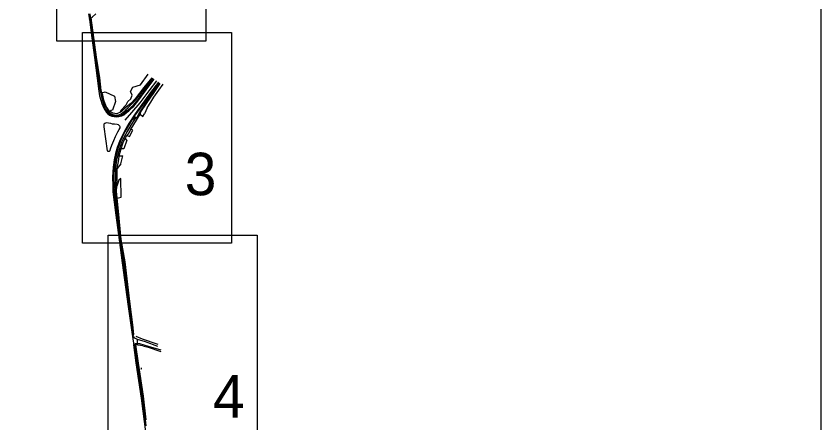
# Model space of a CAD drawing. Extents: x -866693 to -866303, y -1041966 to -1040244.
# Drawn here: x -866389.8 to -866333, y -1041534.9 to -1041506.2 of the extents above; entities that cross this region are included whole.
import ezdxf

# ---------------------------------------------------------------- set-up
doc = ezdxf.new("R2010")
doc.units = 0
doc.layers.add('Formát', color=7, linetype='Continuous')
doc.layers.add('Legenda', color=7, linetype='Continuous')

msp = doc.modelspace()

# ---------------------------------------------------------------- linework, layer by layer
at = {"layer": 'Formát'}
msp.add_lwpolyline([(-866543.01, -1041383.964), (-866333.01, -1041383.964), (-866333.01, -1041680.964), (-866543.01, -1041680.964)], close=True, dxfattribs=at)
at = {"layer": 'Legenda'}
for p, q in [((-866384.553, -1041506.047), (-866384.51, -1041506.433)), ((-866384.388, -1041506.26), (-866384.134, -1041506.041)), ((-866384.589, -1041506.446), (-866384.553, -1041506.379)), ((-866384.589, -1041506.446), (-866384.413, -1041507.37)), ((-866384.553, -1041506.379), (-866384.463, -1041506.308)), ((-866384.51, -1041506.433), (-866384.368, -1041507.364)), ((-866384.463, -1041506.308), (-866384.388, -1041506.26)), ((-866384.319, -1041507.359), (-866384.463, -1041506.308)), ((-866384.413, -1041507.37), (-866384.18, -1041509.114)), ((-866384.368, -1041507.364), (-866384.131, -1041509.098)), ((-866384.086, -1041509.097), (-866384.319, -1041507.359)), ((-866384.18, -1041509.114), (-866383.977, -1041510.562)), ((-866384.131, -1041509.098), (-866383.91, -1041510.543)), ((-866383.863, -1041510.544), (-866384.086, -1041509.097)), ((-866383.977, -1041510.562), (-866383.832, -1041511.476)), ((-866383.91, -1041510.543), (-866383.774, -1041511.45)), ((-866383.759, -1041511.453), (-866383.863, -1041510.544)), ((-866380.983, -1041511.048), (-866380.445, -1041510.294)), ((-866380.192, -1041510.544), (-866380.744, -1041511.231)), ((-866380.688, -1041511.307), (-866380.128, -1041510.566)), ((-866380.614, -1041511.367), (-866380.067, -1041510.598)), ((-866381.697, -1041511.521), (-866381.537, -1041511.209)), ((-866381.537, -1041511.209), (-866380.983, -1041511.048)), ((-866379.869, -1041510.753), (-866380.41, -1041511.478)), ((-866379.662, -1041510.902), (-866380.215, -1041511.627)), ((-866379.628, -1041510.945), (-866380.157, -1041511.689)), ((-866380.116, -1041511.717), (-866379.595, -1041510.958)), ((-866379.687, -1041511.426), (-866379.392, -1041510.988)), ((-866383.832, -1041511.476), (-866383.766, -1041511.793)), ((-866383.774, -1041511.45), (-866383.695, -1041511.778)), ((-866383.703, -1041511.615), (-866383.759, -1041511.453)), ((-866383.703, -1041511.615), (-866383.468, -1041511.542)), ((-866383.651, -1041511.774), (-866383.703, -1041511.615)), ((-866383.695, -1041511.778), (-866383.599, -1041512.119)), ((-866383.575, -1041512.118), (-866383.651, -1041511.774)), ((-866383.468, -1041511.542), (-866382.82, -1041511.84)), ((-866381.575, -1041511.767), (-866381.697, -1041511.521)), ((-866381.671, -1041512.027), (-866381.575, -1041511.767)), ((-866380.744, -1041511.231), (-866381.364, -1041512.04)), ((-866381.314, -1041512.109), (-866380.688, -1041511.307)), ((-866381.221, -1041512.17), (-866380.614, -1041511.367)), ((-866380.215, -1041511.627), (-866381.149, -1041512.883)), ((-866380.41, -1041511.478), (-866381.036, -1041512.316)), ((-866380.157, -1041511.689), (-866381.032, -1041512.948)), ((-866380.255, -1041511.906), (-866380.116, -1041511.717)), ((-866380.043, -1041511.916), (-866379.687, -1041511.426)), ((-866383.766, -1041511.793), (-866383.695, -1041512.106)), ((-866383.695, -1041512.106), (-866383.625, -1041512.32)), ((-866383.625, -1041512.32), (-866383.531, -1041512.609)), ((-866383.599, -1041512.119), (-866383.528, -1041512.332)), ((-866383.497, -1041512.324), (-866383.575, -1041512.118)), ((-866383.528, -1041512.332), (-866383.422, -1041512.587)), ((-866383.396, -1041512.576), (-866383.497, -1041512.324)), ((-866382.743, -1041512.227), (-866382.968, -1041512.839)), ((-866382.82, -1041511.84), (-866382.743, -1041512.227)), ((-866381.678, -1041512.349), (-866382.122, -1041512.705)), ((-866381.986, -1041512.448), (-866381.878, -1041512.215)), ((-866381.878, -1041512.215), (-866381.671, -1041512.027)), ((-866381.364, -1041512.04), (-866381.678, -1041512.349)), ((-866381.036, -1041512.316), (-866381.619, -1041512.989)), ((-866381.562, -1041512.366), (-866381.314, -1041512.109)), ((-866381.51, -1041512.49), (-866381.221, -1041512.17)), ((-866380.957, -1041512.958), (-866380.255, -1041511.906)), ((-866380.527, -1041512.671), (-866380.26, -1041512.266)), ((-866380.26, -1041512.266), (-866380.043, -1041511.916)), ((-866383.531, -1041512.609), (-866383.454, -1041512.781)), ((-866383.454, -1041512.781), (-866383.346, -1041512.954)), ((-866383.422, -1041512.587), (-866383.345, -1041512.753)), ((-866383.297, -1041512.726), (-866383.396, -1041512.576)), ((-866383.345, -1041512.753), (-866383.238, -1041512.925)), ((-866383.189, -1041512.867), (-866383.297, -1041512.726)), ((-866383.238, -1041512.925), (-866383.185, -1041512.988)), ((-866383.141, -1041512.921), (-866383.189, -1041512.867)), ((-866383.051, -1041512.864), (-866383.141, -1041512.921)), ((-866383.059, -1041512.975), (-866383.141, -1041512.921)), ((-866382.968, -1041512.839), (-866383.051, -1041512.864)), ((-866382.398, -1041512.881), (-866381.986, -1041512.448)), ((-866382.353, -1041512.947), (-866382.398, -1041512.881)), ((-866382.122, -1041512.705), (-866382.353, -1041512.947)), ((-866382.229, -1041512.993), (-866382.078, -1041512.884)), ((-866382.184, -1041513.097), (-866381.872, -1041512.824)), ((-866382.106, -1041512.975), (-866382.052, -1041512.925)), ((-866381.977, -1041512.867), (-866382.101, -1041512.97)), ((-866381.956, -1041512.888), (-866382.08, -1041512.991)), ((-866382.078, -1041512.884), (-866382.032, -1041512.808)), ((-866382.078, -1041512.884), (-866382.044, -1041512.917)), ((-866382.052, -1041512.925), (-866382.044, -1041512.917)), ((-866382.044, -1041512.917), (-866382.034, -1041512.909)), ((-866382.034, -1041512.909), (-866381.977, -1041512.867)), ((-866382.032, -1041512.808), (-866381.883, -1041512.663)), ((-866381.956, -1041512.888), (-866381.977, -1041512.867)), ((-866381.883, -1041512.663), (-866381.68, -1041512.483)), ((-866381.872, -1041512.824), (-866381.648, -1041512.62)), ((-866381.68, -1041512.483), (-866381.562, -1041512.366)), ((-866381.648, -1041512.62), (-866381.51, -1041512.49)), ((-866381.149, -1041512.883), (-866381.377, -1041513.194)), ((-866380.527, -1041512.671), (-866380.696, -1041513.08)), ((-866383.346, -1041512.954), (-866383.235, -1041513.047)), ((-866383.235, -1041513.047), (-866383.139, -1041513.124)), ((-866383.185, -1041512.988), (-866383.085, -1041513.057)), ((-866383.139, -1041513.124), (-866382.986, -1041513.201)), ((-866383.085, -1041513.057), (-866382.939, -1041513.128)), ((-866382.903, -1041513.052), (-866383.059, -1041512.975)), ((-866382.986, -1041513.201), (-866382.845, -1041513.234)), ((-866382.939, -1041513.128), (-866382.831, -1041513.161)), ((-866382.804, -1041513.072), (-866382.903, -1041513.052)), ((-866382.845, -1041513.234), (-866382.698, -1041513.246)), ((-866382.831, -1041513.161), (-866382.693, -1041513.18)), ((-866382.652, -1041513.081), (-866382.804, -1041513.072)), ((-866382.698, -1041513.246), (-866382.504, -1041513.232)), ((-866382.693, -1041513.18), (-866382.512, -1041513.159)), ((-866382.353, -1041512.947), (-866382.652, -1041513.081)), ((-866382.512, -1041513.159), (-866382.342, -1041513.092)), ((-866382.504, -1041513.232), (-866382.319, -1041513.178)), ((-866382.342, -1041513.092), (-866382.229, -1041512.993)), ((-866382.319, -1041513.178), (-866382.184, -1041513.097)), ((-866382.106, -1041512.975), (-866382.101, -1041512.97)), ((-866382.08, -1041512.991), (-866382.106, -1041512.975)), ((-866382.08, -1041512.991), (-866382.101, -1041512.97)), ((-866381.619, -1041512.989), (-866382.093, -1041513.536)), ((-866381.377, -1041513.194), (-866381.76, -1041513.801)), ((-866381.357, -1041513.418), (-866381.656, -1041513.89)), ((-866381.522, -1041513.97), (-866381.019, -1041513.103)), ((-866381.353, -1041513.303), (-866381.469, -1041513.459)), ((-866381.469, -1041513.459), (-866381.447, -1041513.476)), ((-866381.469, -1041513.459), (-866381.449, -1041513.477)), ((-866381.333, -1041513.321), (-866381.449, -1041513.477)), ((-866381.449, -1041513.477), (-866381.447, -1041513.476)), ((-866381.447, -1041513.476), (-866381.395, -1041513.413)), ((-866381.381, -1041513.399), (-866381.395, -1041513.413)), ((-866381.369, -1041513.379), (-866381.381, -1041513.399)), ((-866381.357, -1041513.418), (-866381.381, -1041513.399)), ((-866381.333, -1041513.322), (-866381.369, -1041513.379)), ((-866381.253, -1041513.346), (-866381.357, -1041513.418)), ((-866381.333, -1041513.321), (-866381.353, -1041513.303)), ((-866381.353, -1041513.303), (-866381.333, -1041513.322)), ((-866381.333, -1041513.322), (-866381.333, -1041513.321)), ((-866381.032, -1041512.948), (-866381.253, -1041513.346)), ((-866381.019, -1041513.103), (-866380.957, -1041512.958)), ((-866381.019, -1041513.103), (-866380.821, -1041513.266)), ((-866380.821, -1041513.266), (-866380.696, -1041513.08)), ((-866383.575, -1041513.89), (-866383.578, -1041514.013)), ((-866383.578, -1041514.013), (-866383.343, -1041515.693)), ((-866383.561, -1041513.829), (-866383.575, -1041513.89)), ((-866383.512, -1041513.771), (-866383.561, -1041513.829)), ((-866383.458, -1041513.746), (-866383.512, -1041513.771)), ((-866383.373, -1041513.724), (-866383.458, -1041513.746)), ((-866383.248, -1041513.753), (-866383.373, -1041513.724)), ((-866383.088, -1041513.782), (-866383.248, -1041513.753)), ((-866382.95, -1041513.814), (-866383.088, -1041513.782)), ((-866382.813, -1041513.825), (-866382.95, -1041513.814)), ((-866382.632, -1041513.84), (-866382.813, -1041513.825)), ((-866382.539, -1041513.861), (-866382.632, -1041513.84)), ((-866382.486, -1041513.9), (-866382.539, -1041513.861)), ((-866382.439, -1041513.954), (-866382.486, -1041513.9)), ((-866382.419, -1041514.01), (-866382.439, -1041513.954)), ((-866382.422, -1041514.075), (-866382.419, -1041514.01)), ((-866381.76, -1041513.801), (-866382.071, -1041514.322)), ((-866381.656, -1041513.89), (-866381.919, -1041514.34)), ((-866381.664, -1041514.168), (-866381.522, -1041513.97)), ((-866382.751, -1041514.692), (-866382.58, -1041514.357)), ((-866382.58, -1041514.357), (-866382.488, -1041514.183)), ((-866382.488, -1041514.183), (-866382.422, -1041514.075)), ((-866382.071, -1041514.322), (-866382.271, -1041514.723)), ((-866381.919, -1041514.34), (-866382.161, -1041514.756)), ((-866382.036, -1041514.76), (-866381.929, -1041514.623)), ((-866381.929, -1041514.623), (-866381.787, -1041514.434)), ((-866381.929, -1041514.623), (-866381.766, -1041514.699)), ((-866381.787, -1041514.434), (-866381.664, -1041514.168)), ((-866381.766, -1041514.699), (-866381.523, -1041514.249)), ((-866381.523, -1041514.249), (-866381.664, -1041514.168)), ((-866383.004, -1041515.29), (-866382.875, -1041514.969)), ((-866382.875, -1041514.969), (-866382.751, -1041514.692)), ((-866382.425, -1041515.049), (-866382.559, -1041515.498)), ((-866382.324, -1041515.095), (-866382.47, -1041515.553)), ((-866382.271, -1041514.723), (-866382.425, -1041515.049)), ((-866382.364, -1041515.617), (-866382.201, -1041515.103)), ((-866382.161, -1041514.756), (-866382.324, -1041515.095)), ((-866382.201, -1041515.103), (-866382.036, -1041514.76)), ((-866381.946, -1041514.949), (-866382.159, -1041515.546)), ((-866381.946, -1041514.949), (-866382.04, -1041514.833)), ((-866383.343, -1041515.693), (-866383.298, -1041515.73)), ((-866383.298, -1041515.73), (-866383.238, -1041515.732)), ((-866383.238, -1041515.732), (-866383.183, -1041515.716)), ((-866383.183, -1041515.716), (-866383.129, -1041515.676)), ((-866383.129, -1041515.676), (-866383.094, -1041515.549)), ((-866383.094, -1041515.549), (-866383.004, -1041515.29)), ((-866382.559, -1041515.498), (-866382.681, -1041515.917)), ((-866382.47, -1041515.553), (-866382.59, -1041515.949)), ((-866382.48, -1041516.043), (-866382.364, -1041515.617)), ((-866382.159, -1041515.546), (-866382.339, -1041515.558)), ((-866382.681, -1041515.917), (-866382.771, -1041516.352)), ((-866382.59, -1041515.949), (-866382.675, -1041516.368)), ((-866382.637, -1041516.953), (-866382.506, -1041516.315)), ((-866382.506, -1041516.315), (-866382.48, -1041516.043)), ((-866382.48, -1041516.043), (-866382.225, -1041516.041)), ((-866382.368, -1041516.611), (-866382.225, -1041516.041)), ((-866382.847, -1041516.868), (-866382.877, -1041517.544)), ((-866382.771, -1041516.352), (-866382.847, -1041516.868)), ((-866382.675, -1041516.368), (-866382.757, -1041516.88)), ((-866382.757, -1041516.88), (-866382.755, -1041517.553)), ((-866382.368, -1041516.611), (-866382.637, -1041516.953)), ((-866382.641, -1041517.603), (-866382.637, -1041516.953)), ((-866382.877, -1041517.544), (-866382.869, -1041518.166)), ((-866382.755, -1041517.553), (-866382.768, -1041518.168)), ((-866382.658, -1041518.2), (-866382.641, -1041517.603)), ((-866382.522, -1041517.767), (-866382.658, -1041518.2)), ((-866382.369, -1041517.654), (-866382.522, -1041517.767)), ((-866382.35, -1041518.959), (-866382.369, -1041517.654)), ((-866382.869, -1041518.166), (-866382.835, -1041518.564)), ((-866382.835, -1041518.564), (-866382.648, -1041520.221)), ((-866382.768, -1041518.168), (-866382.752, -1041518.545)), ((-866382.752, -1041518.545), (-866382.58, -1041520.207)), ((-866382.676, -1041518.533), (-866382.658, -1041518.2)), ((-866382.637, -1041519.038), (-866382.676, -1041518.533)), ((-866382.637, -1041519.038), (-866382.35, -1041518.959)), ((-866382.534, -1041519.962), (-866382.637, -1041519.038)), ((-866382.648, -1041520.221), (-866382.422, -1041521.959)), ((-866382.58, -1041520.207), (-866382.375, -1041521.949)), ((-866382.341, -1041521.942), (-866382.534, -1041519.962)), ((-866382.422, -1041521.959), (-866382.239, -1041523.573)), ((-866382.375, -1041521.949), (-866382.165, -1041523.547)), ((-866382.07, -1041523.533), (-866382.341, -1041521.942)), ((-866382.239, -1041523.573), (-866382.153, -1041524.091)), ((-866382.165, -1041523.547), (-866382.097, -1041524.086)), ((-866381.746, -1041526.32), (-866382.07, -1041523.533)), ((-866382.153, -1041524.091), (-866381.824, -1041526.587)), ((-866382.097, -1041524.086), (-866381.78, -1041526.408)), ((-866381.78, -1041526.408), (-866381.568, -1041528.048)), ((-866381.534, -1041527.975), (-866381.746, -1041526.32)), ((-866381.824, -1041526.587), (-866381.599, -1041528.287)), ((-866381.568, -1041528.048), (-866381.488, -1041528.661)), ((-866381.463, -1041528.664), (-866381.534, -1041527.975)), ((-866381.599, -1041528.287), (-866381.538, -1041528.667)), ((-866381.538, -1041528.667), (-866381.519, -1041528.667)), ((-866381.456, -1041528.819), (-866381.538, -1041528.667)), ((-866381.488, -1041528.661), (-866381.519, -1041528.667)), ((-866381.519, -1041528.667), (-866381.463, -1041528.664)), ((-866381.463, -1041528.664), (-866381.488, -1041528.661)), ((-866380.85, -1041528.979), (-866381.292, -1041528.792)), ((-866381.389, -1041528.912), (-866381.456, -1041528.819)), ((-866381.446, -1041529.389), (-866381.333, -1041529.296)), ((-866381.446, -1041529.389), (-866381.344, -1041529.378)), ((-866381.344, -1041529.378), (-866381.408, -1041529.386)), ((-866381.188, -1041529.016), (-866381.389, -1041528.912)), ((-866380.827, -1041529.462), (-866381.344, -1041529.378)), ((-866381.344, -1041529.378), (-866381.155, -1041530.672)), ((-866381.333, -1041529.296), (-866381.192, -1041529.277)), ((-866381.192, -1041529.277), (-866381.188, -1041529.016)), ((-866381.192, -1041529.277), (-866381.06, -1041529.289)), ((-866380.644, -1041529.172), (-866381.188, -1041529.016)), ((-866381.06, -1041529.289), (-866380.437, -1041529.473)), ((-866379.732, -1041529.362), (-866380.85, -1041528.979)), ((-866379.755, -1041529.491), (-866380.644, -1041529.172)), ((-866381.467, -1041529.422), (-866381.446, -1041529.389)), ((-866381.408, -1041529.386), (-866381.446, -1041529.389)), ((-866381.284, -1041530.65), (-866381.446, -1041529.389)), ((-866381.408, -1041529.386), (-866381.22, -1041530.658)), ((-866380.827, -1041529.462), (-866380.441, -1041529.54)), ((-866380.441, -1041529.54), (-866379.548, -1041529.856)), ((-866380.437, -1041529.473), (-866379.541, -1041529.744)), ((-866380.914, -1041533.095), (-866381.284, -1041530.65)), ((-866381.22, -1041530.658), (-866380.858, -1041533.036)), ((-866381.155, -1041530.672), (-866380.806, -1041533.007)), ((-866380.675, -1041534.692), (-866380.914, -1041533.095)), ((-866380.858, -1041533.036), (-866380.652, -1041534.681)), ((-866380.806, -1041533.007), (-866380.6, -1041534.678)), ((-866380.675, -1041534.692), (-866380.6, -1041534.678)), ((-866380.652, -1041534.681), (-866380.675, -1041534.692)), ((-866380.6, -1041534.678), (-866380.652, -1041534.681)), ((-866380.652, -1041534.681), (-866380.599, -1041535.096))]:
    msp.add_line(p, q, dxfattribs=at)
for points in [[(-866386.886, -1041493.105), (-866376.386, -1041493.105), (-866376.386, -1041507.955), (-866386.886, -1041507.955)], [(-866385.077, -1041507.358), (-866374.577, -1041507.358), (-866374.577, -1041522.208), (-866385.077, -1041522.208)], [(-866383.269, -1041521.636), (-866372.769, -1041521.636), (-866372.769, -1041536.486), (-866383.269, -1041536.486)]]:
    msp.add_lwpolyline(points, close=True, dxfattribs=at)
for points in [[(-866384.649, -1041506.04), (-866384.589, -1041506.446), (-866384.455, -1041507.373), (-866384.224, -1041509.114), (-866384.032, -1041510.565), (-866383.914, -1041511.5), (-866383.867, -1041511.816), (-866383.777, -1041512.124), (-866383.706, -1041512.358), (-866383.597, -1041512.64), (-866383.504, -1041512.815), (-866383.387, -1041512.995), (-866383.279, -1041513.099), (-866383.169, -1041513.175), (-866383.007, -1041513.255), (-866382.853, -1041513.279), (-866382.704, -1041513.298), (-866382.517, -1041513.278), (-866382.313, -1041513.219), (-866382.163, -1041513.158), (-866381.97, -1041513.001), (-866381.82, -1041512.875), (-866381.601, -1041512.673), (-866381.447, -1041512.548), (-866381.178, -1041512.199), (-866380.579, -1041511.396), (-866380.011, -1041510.637)], [(-866379.726, -1041510.849), (-866380.272, -1041511.587), (-866381.203, -1041512.844), (-866381.412, -1041513.151), (-866381.801, -1041513.765), (-866382.109, -1041514.3), (-866382.313, -1041514.694), (-866382.477, -1041515.03), (-866382.64, -1041515.473), (-866382.758, -1041515.89), (-866382.854, -1041516.344), (-866382.924, -1041516.862), (-866382.952, -1041517.55), (-866382.947, -1041518.15), (-866382.941, -1041518.582), (-866382.716, -1041520.23), (-866382.485, -1041521.966), (-866382.269, -1041523.604), (-866382.202, -1041524.12), (-866381.848, -1041526.688), (-866381.626, -1041528.324), (-866381.467, -1041529.422), (-866381.46, -1041529.543), (-866381.31, -1041530.643), (-866380.949, -1041533.136), (-866380.599, -1041535.718)], [(-866380.971, -1041531.082), (-866380.921, -1041531.082)], [(-866380.946, -1041531.007), (-866380.946, -1041531.082)]]:
    msp.add_lwpolyline(points, dxfattribs=at)

# ---------------------------------------------------------------- texts
at = {"layer": 'Formát'}
for s, p in [('3', (-866377.867, -1041518.832)), ('4', (-866375.872, -1041534.513))]:
    msp.add_text(s, height=3, dxfattribs=at).set_placement(p)

doc.saveas('drawing.dxf')
